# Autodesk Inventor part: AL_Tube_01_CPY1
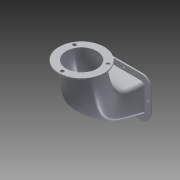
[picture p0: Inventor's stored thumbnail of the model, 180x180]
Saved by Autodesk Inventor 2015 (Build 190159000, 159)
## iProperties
Created: 2006-10
Part Number: AL_Tube_01_CPY1
Material: Aluminum-6061
Description: Exhaust Tube - Transitional
Document SubType Name: Modeling
Designer: Autodesk, Inc.
Mass: 16972.7 g
Surface Area: 12672.8 cm^2
Volume: 6263 cm^3
Density: 2.71 g/cm^3
Appearance: Aluminum - Flat
Author: Autodesk, Inc.
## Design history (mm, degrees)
node "Distance Plane"
sketch "Sketch2"
  geometry: L1 (-78.628, 403.823)-(-78.628, 548.123); L2 (-78.628, 403.823)-(46.339, 331.673); L3 (-78.628, 403.823)-(-203.596, 331.673); C1 r 114.3 at (-78.628, 403.823); C2 r 169.3 at (-78.628, 403.823); C3 r 12.7 at (-78.628, 548.123); C4 r 12.7 at (46.339, 331.673); C5 r 12.7 at (-203.596, 331.673); A1 r 144.3 centre (-78.628, 403.823) between (-78.628, 548.123) and (46.339, 331.673); 1 further point
  constraints: 6 centre point, 6 end point, 3 point on circle, 2 coincident, 2 equal radius, 1 vertical
  dimensions: "d22" = 228.6 diameter of C1; "d23" = 338.6 diameter of C2 (computed from d22); "d24" = 288.6 diameter of A1 (computed from d22); "d88" = 120 deg angle of L3 L1; "d89" = 120 deg angle of L2 L1 (= d88); "d113" = 25.4 diameter of C3
node "Angle Plane"
  workaxis "Work Axis1"
feature "Stitch Surface4" dims "d138" = 0.254 (derived)
thicken "Thicken4" dims "d137" = 10.16
body "Solid1"
sketch "3D Sketch3" dims "d14" = 25.4, "d15" = 25.4
body "Srf2"
body "Srf3"
body "Srf1"
body "Srf4"
patch "Boundary Patch1"
patch "Boundary Patch2"
feature "LoftSrf4" dims "d115" = 0, "d116" = 90 deg, "d117" = 0, "d118" = 90 deg, "d119" = 0, "d120" = 90 deg, "d121" = 0, "d122" = 0, "d123" = 4042.21261, "d124" = 10.00133, "d125" = 660.87569, "d126" = 10, "d127" = 5491.09151, "d128" = 10.00086, "d129" = 453.91524, "d130" = 6.86839, "d131" = 3999.992, "d132" = 7.93428, "d133" = 257.666, "d134" = 3.89886, "d135" = 3999.992, "d136" = 8.66046
other parameters: "d2" = 406.4, "d26" = 10 deg, "d114" = 12.7
